// TIA Portal project "SIKO_template_S7_300_UNI_PNvABC_V1.01" (V14)

(* hardware
DEVICE "S7300/ET200M-Station_1"  S7-300 station
   slot 0: "Profilschiene_0"  Rail  6ES7 390-1***0-0AA0
   slot 2: "PLC_1"  CPU 314C-2 PN/DP  6ES7 314-6EH04-0AB0  V3.3
      slot 2: "PROFINET-Schnittstelle_1"  PN-IO
         slot 1: "Port_1"  Port
         slot 2: "Port_2"  Port
      slot 5: "DI 24/DO 16_1"  DI24/DO16
      slot 6: "AI 5/AO 2_1"  AI5/AO2
      slot 7: "Zählen_1"  Counter
      slot 8: "Positionieren_1"  Positioning
DEVICE "GSD-Geraet_1"  GSD.Device.PN
   slot 0: "Baugruppenträger"  Rack  V1.0
   slot 0: "ABC-PRT"  RT Standard  AB7013-C  V3.03
      slot 0: "RT Standard"  RT Standard
      slot 1: "Interface"  Interface
         slot 1: "RJ45 100 MBit/s"  RJ45 100 MBit/s
   slot 1: "Ein-/Ausgänge 004 bytes_1"  Input/Output 004 bytes
      slot 0: "Ein-/Ausgänge 004 bytes"  Input/Output 004 bytes
   slot 2: "Ein-/Ausgänge 016 bytes_1_AG03_1"  Input/Output 016 bytes
      slot 0: "Ein-/Ausgänge 016 bytes"  Input/Output 016 bytes
   slot 3: "Ein-/Ausgänge 016 bytes_1_AG05"  Input/Output 016 bytes
      slot 0: "Ein-/Ausgänge 016 bytes"  Input/Output 016 bytes
   slot 4: "Ein-/Ausgänge 016 bytes_1_AG06"  Input/Output 016 bytes
      slot 0: "Ein-/Ausgänge 016 bytes"  Input/Output 016 bytes
   slot 5: "Ein-/Ausgänge 016 bytes_1_AP04"  Input/Output 016 bytes
      slot 0: "Ein-/Ausgänge 016 bytes"  Input/Output 016 bytes
   slot 6: "Ein-/Ausgänge 016 bytes_1_AP04S"  Input/Output 016 bytes
      slot 0: "Ein-/Ausgänge 016 bytes"  Input/Output 016 bytes
   slot 7: "Ein-/Ausgänge 016 bytes_1_AP10"  Input/Output 016 bytes
      slot 0: "Ein-/Ausgänge 016 bytes"  Input/Output 016 bytes
   slot 8: "Ein-/Ausgänge 016 bytes_1_AP10S"  Input/Output 016 bytes
      slot 0: "Ein-/Ausgänge 016 bytes"  Input/Output 016 bytes
   slot 9: "Ein-/Ausgänge 016 bytes_1_AP10T"  Input/Output 016 bytes
      slot 0: "Ein-/Ausgänge 016 bytes"  Input/Output 016 bytes
*)

// ===== PLC "PLC_1"  CPU 314C-2 PN/DP =====
// protected blocks, not shown: "SIKO_AG03_1_CSW_POS", "SIKO_AG05_CSW_POS", "SIKO_AP04S_CSW_POS", "SIKO_AP04_CSW_POS", "SIKO_AP10S_CSW_POS", "SIKO_AP10T_CSW_POS", "SIKO_AP10_CSW_POS", "SIKO_SN5_COM_EPN", "SIKO_SN5_PARA"

TYPE "DC_Com"
VERSION : 0.1
   STRUCT
      bc00 : Bool;
      bc01 : Bool;
      bc02 : Bool;
      bc03 : Bool;
      bc04 : Bool;
      bc05 : Bool;
      bc06 : Bool;
      bc07 : Bool;
      bc08 : Bool;
      bc09 : Bool;
      bc10 : Bool;
      bc11 : Bool;
      bc12 : Bool;
      bc13 : Bool;
      bc14 : Bool;
      bc15 : Bool;
      bcCal : Bool;
      bs00 : Bool;
      bs01 : Bool;
      bs02 : Bool;
      bs03 : Bool;
      bs04 : Bool;
      bs06 : Bool;
      bs07 : Bool;
      bs08 : Bool;
      bs09 : Bool;
      bs10 : Bool;
      bs11 : Bool;
      bs12 : Bool;
      bs13 : Bool;
      bs14 : Bool;
      bs15 : Bool;
      bsCalExec : Bool;
      nPara1Adr : Byte := BYTE#16#FE;
      nPara2Adr : Byte := BYTE#16#FE;
      nPara3Adr : Byte := BYTE#16#FE;
      nPara3Cmd : Byte;
      nPara3Val : DInt;
      bPara3Write : Bool;
      nPara1AdrRec : Byte;
      nPara1ValRec : DInt;
      nPara2AdrRec : Byte;
      nPara2ValRec : DInt;
      nPara3AdrRec : Byte;
      nPara3ValRec : DInt;
      bPara1FD : Bool;
      bPara2FD : Bool;
      bPara3FD : Bool;
      bsFaultDataRec : Bool;
      nErrCode1 : Byte;
      nErrCode2 : Byte;
      bs05 : Bool;
   END_STRUCT;
END_TYPE

// folder: SystemBlocksFolder/ReportSystemErrorFolder

DATA_BLOCK "RSE_DIAGNOSTIC_STATUS_DB"   // DB127
TITLE = Systemfehler melden Diagnose Baustein
{ S7_Optimized_Access := 'FALSE' }
AUTHOR : SIMATIC
FAMILY : RSEDIAG
NAME : RSE7
VERSION : 1.0
// Dieser DB ist Bestandteil von Systemfehler melden und wird durch den SFM FB aktualisiert.
//  Er ist eine Schnittstelle für die Unterstützung der Systemdiagnose über den CPU Webserver.
   VAR
      Directory : Struct
         D_Version : Word := WORD#16#0100;   // Version, die SFM unterstützt
         D_pGlobalState : Word := WORD#16#0010;   // Byte-Offset bis zum Anfang des Teils "GlobalState"
         D_pQuery : Word := WORD#16#0014;   // Byte-Offset bis zum Anfang des Teils "Query"
         D_pComponent : Word := WORD#16#0020;   // Byte-Offset bis zum Anfang des Teils "Component"
         D_pError : Word := WORD#16#0024;   // Byte-Offset bis zum Anfang des Teils "Error"
         D_pState : Word := WORD#16#0028;   // Byte-Offset bis zum Anfang des Teils "State"
         D_pAlarm : Word := WORD#16#005A;   // Byte-Offset bis zum Anfang des Teils "Alarm"
         D_pSubComponent : Word := WORD#16#0082;   // Byte-Offset bis zum Anfang des Teils "Subcomponent"
      END_STRUCT;
      GlobalState : Struct
         G_EventCount : Word := WORD#16#0000;   // ID des letzten Ereignisses (Zähler)
         G_StartReporting : Bool := FALSE;   // Anlaufauswertung läuft
      END_STRUCT;
      Query : Struct
         Q_ClientID_User : DWord := DWORD#16#0000_0000;   // ID des Clients
         Q_ClientID_Intern : DWord := DWORD#16#0000_0000;   // ID des Clients (intern)
         Q_WithSubComponent : Bool := FALSE;   // Mit/Ohne Status der untergeordneten Komponenten (langsamer)
         Q_SubComponentAlarm : Bool := FALSE;   // AS-iMaster gibt AS-iSlave Alarme zurück
         Q_Reserved2 : Bool := FALSE;   // Reserviert
         Q_Reserved3 : Bool := FALSE;   // Reserviert
         Q_Reserved4 : Bool := FALSE;   // Reserviert
         Q_Reserved5 : Bool := FALSE;   // Reserviert
         Q_Reserved6 : Bool := FALSE;   // Reserviert
         Q_Reserved7 : Bool := FALSE;   // Reserviert
         Q_Start : Bool := FALSE;   // Abfrage starten
         Q_Error : Byte := BYTE#16#00;   // Interner Fehler bei der Abfrage
         Q_Reserved8 : Byte := BYTE#16#00;   // Reserviert
      END_STRUCT;
      Component : Struct
         C_AddressMode : Byte := BYTE#16#00;   // Adressierungsmodus der Baugruppe
         C_Reserved1 : Byte := BYTE#16#00;   // Reserviert
         C_ComponentID : Word := WORD#16#0000;   // Hardware ID der Komponente (intern)
      END_STRUCT;
      Error : Struct
         E_ErrorNo : Word := WORD#16#0000;   // Index des angeforderten/tatsächlichen Fehlers
         E_LastError : Bool := FALSE;   // TRUE, falls E_ErrorNo den Index des letzten Fehlers enthält, ansonsten FALSE
      END_STRUCT;
      State : Struct
         S_Hierarchy : Byte := BYTE#16#00;   // Reserviert
         S_Periphery : Byte := BYTE#16#00;   // Reserviert
         S_SupFault : Bool := FALSE;   // Die Komponente ist nicht erreichbar
         S_NotAvailable : Bool := FALSE;   // Die Komponente ist nicht vorhanden
         S_Faulty : Bool := FALSE;   // Die Komponente ist gestört; der Teil "Alarm" ist nicht leer
         S_MoreErrors : Bool := FALSE;   // Es liegen mehr Fehler an, als SFM speichern kann.
         S_Maintenance1 : Bool := FALSE;   // Ein Wartungsbedarf liegt an
         S_Maintenance2 : Bool := FALSE;   // Eine Wartungsanforderung liegt an
         S_Deactivated : Bool := FALSE;   // Die Komponente wurde deaktiviert
         S_Reserved2 : Bool := FALSE;   // Reserviert
         S_SubFault : Bool := FALSE;   // Eine untergeordnete Komponente ist gestört
         S_SubMaintenance1 : Bool := FALSE;   // Ein Wartungsbedarf liegt an einer untergeordneten Komponente an
         S_SubMaintenance2 : Bool := FALSE;   // Eine Wartungsanforderung liegt an einer untergeordneten Komponente an
         S_SubDeactivated : Bool := FALSE;   // Mindestens eine untergeordnete Komponente ist deaktiviert
         S_Reserved4 : Bool := FALSE;   // Reserviert
         S_Reserved5 : Bool := FALSE;   // Reserviert
         S_Reserved6 : Bool := FALSE;   // Reserviert
         S_Reserved7 : Bool := FALSE;   // Reserviert
         S_TIAMS : DWord := DWORD#16#0000_0000;   // Maintenance State der Komponente
         S_TIAMSChannelExist : DWord := DWORD#16#0000_0000;   // Maintenance State: Projektierte Kanäle
         S_TIAMSChannelOK : DWord := DWORD#16#0000_0000;   // Maintenance State: Gestörte Kanäle
         S_ChannelCount : Word := WORD#16#0000;   // Anzahl Kanäle; nur gültig wenn Q_WithSubComponent gesetzt ist
         S_ChannelVector : Array[0..255] of Bool;   // Liste der betroffenen Kanäle; nur gültig wenn Q_WithSubComponent gesetzt ist
      END_STRUCT;
      Alarm : Struct
         A_ComponentID : Word := WORD#16#0000;   // Hardware-ID der Komponente (intern)
         A_TextID1 : Word := WORD#16#0000;   // ID des ersten Fehlertexts
         A_TextLexikonID1 : Word := WORD#16#0000;   // ID des ersten Fehlertextlexikons
         A_HelpTextLexikonID1 : Word := WORD#16#0000;   // ID des ersten Hilfetextlexikons
         A_MapTextID : Word := WORD#16#0000;   // ID des ersten Fehlertexts in der Exportdatei (HMI)
         A_MapHelpTextID : Word := WORD#16#0000;   // ID des ersten Hilfetexts in der Exportdatei (HMI)
         A_TextID2 : Word := WORD#16#0000;   // ID des zweiten Fehlertexts
         A_TextLexikonID2 : Word := WORD#16#0000;   // ID des zweiten Fehlertextlexikons
         A_HelpTextLexikonID2 : Word := WORD#16#0000;   // ID des zweiten Hilfetextlexikons
         A_MapTextID2 : Word := WORD#16#0000;   // ID des zweiten Fehlertexts in der Exportdatei (HMI)
         A_MapHelpTextID2 : Word := WORD#16#0000;   // ID des zweiten Hilfetexts in der Exportdatei (HMI)
         A_AlarmID : DWord := DWORD#16#0000_0000;   // Meldenummer
         A_ValueCount : Word := WORD#16#000C;   // Anzahl der belegten weiteren Bytes
         A_AssociatedValue : Array[1..6] of Word;   // Begleitwerte der Meldung
      END_STRUCT;
      SubComponent : Struct
         U_SubComponentCount : Word := WORD#16#0000;   // Anzahl der untergeordneten Komponenten
         U_SubComponentFault : Array[1..12] of Byte;   // Liste des Status der untergeordneten Komponenten, 1 Byte pro Komponente
      END_STRUCT;
   END_VAR
BEGIN
END_DATA_BLOCK

// folder: (top level)

ORGANIZATION_BLOCK "OB1"   // OB1, LAD
TITLE = "Main Program Sweep (Cycle)"
{ S7_Optimized_Access := 'FALSE' }
VERSION : 0.1
   VAR_TEMP
      OB1_EV_CLASS : Byte;   // Bits 0-3 = 1 (Coming event), Bits 4-7 = 1 (Event class 1)
      OB1_SCAN_1 : Byte;   // 1 (Cold restart scan 1 of OB 1), 3 (Scan 2-n of OB 1)
      OB1_PRIORITY : Byte;   // Priority of OB Execution
      OB1_OB_NUMBR : Byte;   // 1 (Organization block 1, OB1)
      OB1_RESERVED_1 : Byte;   // Reserved for system
      OB1_RESERVED_2 : Byte;   // Reserved for system
      OB1_PREV_CYCLE : Int;   // Cycle time of previous OB1 scan (milliseconds)
      OB1_MIN_CYCLE : Int;   // Minimum cycle time of OB1 (milliseconds)
      OB1_MAX_CYCLE : Int;   // Maximum cycle time of OB1 (milliseconds)
      OB1_DATE_TIME : Date_And_Time;   // Date and time OB1 started
      DC_Com_AG05 : "DC_Com";
   END_VAR
BEGIN

REGION Network 1
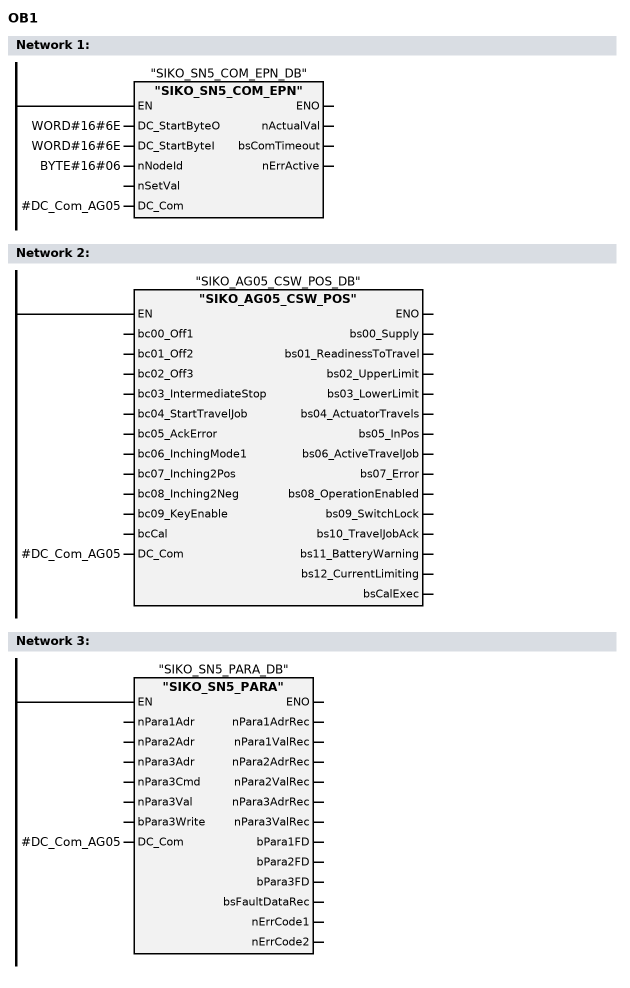
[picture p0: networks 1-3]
   RUNG wire#powerrail
      "SIKO_SN5_COM_EPN_DB"(DC_StartByteO := WORD#16#6E, DC_StartByteI := WORD#16#6E, nNodeId := BYTE#16#06, nSetVal :=, DC_Com := #DC_Com_AG05, nActualVal =>, bsComTimeout =>, nErrActive =>)
   END_RUNG
   // the same network as SCL:
   "SIKO_SN5_COM_EPN_DB"(DC_StartByteO := WORD#16#6E,   // "SIKO_SN5_COM_EPN"
                         DC_StartByteI := WORD#16#6E,
                         nNodeId := BYTE#16#06,
                         DC_Com := #DC_Com_AG05);
END_REGION

REGION Network 2
   RUNG wire#powerrail
      "SIKO_AG05_CSW_POS_DB"(bc00_Off1 :=, bc01_Off2 :=, bc02_Off3 :=, bc03_IntermediateStop :=, bc04_StartTravelJob :=, bc05_AckError :=, bc06_InchingMode1 :=, bc07_Inching2Pos :=, bc08_Inching2Neg :=, bc09_KeyEnable :=, bcCal :=, bs00_Supply =>, bs01_ReadinessToTravel =>, bs02_UpperLimit =>, bs03_LowerLimit =>, bs04_ActuatorTravels =>, bs05_InPos =>, bs06_ActiveTravelJob =>, bs07_Error =>, bs08_OperationEnabled =>, bs09_SwitchLock =>, bs10_TravelJobAck =>, bs11_BatteryWarning =>, bs12_CurrentLimiting =>, bsCalExec =>, DC_Com := #DC_Com_AG05)
   END_RUNG
   // the same network as SCL:
   "SIKO_AG05_CSW_POS_DB"(DC_Com := #DC_Com_AG05);   // "SIKO_AG05_CSW_POS"
END_REGION

REGION Network 3
   RUNG wire#powerrail
      "SIKO_SN5_PARA_DB"(nPara1Adr :=, nPara2Adr :=, nPara3Adr :=, nPara3Cmd :=, nPara3Val :=, bPara3Write :=, DC_Com := #DC_Com_AG05, nPara1AdrRec =>, nPara1ValRec =>, nPara2AdrRec =>, nPara2ValRec =>, nPara3AdrRec =>, nPara3ValRec =>, bPara1FD =>, bPara2FD =>, bPara3FD =>, bsFaultDataRec =>, nErrCode1 =>, nErrCode2 =>)
   END_RUNG
   // the same network as SCL:
   "SIKO_SN5_PARA_DB"(DC_Com := #DC_Com_AG05);   // "SIKO_SN5_PARA"
END_REGION

REGION Network 4 (STL): Call system diagnostics block / Systemdiagnosebaustein aufrufen
         CALL  "RSE_FB", "RSE_DB";
END_REGION
END_ORGANIZATION_BLOCK

ORGANIZATION_BLOCK "OB82"   // OB82, STL
TITLE = "I/O Point Fault"
{ S7_Optimized_Access := 'FALSE' }
VERSION : 0.1
   VAR_TEMP
      OB82_EV_CLASS : Byte;   // 16#39, Event class 3, Entering event state, Internal fault event
      OB82_FLT_ID : Byte;   // 16#XX, Fault identifcation code
      OB82_PRIORITY : Byte;   // Priority of OB Execution
      OB82_OB_NUMBR : Byte;   // 82 (Organization block 82, OB82)
      OB82_RESERVED_1 : Byte;   // Reserved for system
      OB82_IO_FLAG : Byte;   // Input (01010100), Output (01010101)
      OB82_MDL_ADDR : Word;   // Base address of module with fault
      OB82_MDL_DEFECT : Bool;   // Module defective
      OB82_INT_FAULT : Bool;   // Internal fault
      OB82_EXT_FAULT : Bool;   // External fault
      OB82_PNT_INFO : Bool;   // Point information
      OB82_EXT_VOLTAGE : Bool;   // External voltage low
      OB82_FLD_CONNCTR : Bool;   // Field wiring connector missing
      OB82_NO_CONFIG : Bool;   // Module has no configuration data
      OB82_CONFIG_ERR : Bool;   // Module has configuration error
      OB82_MDL_TYPE : Byte;   // Type of module
      OB82_SUB_MDL_ERR : Bool;   // Sub-Module is missing or has error
      OB82_COMM_FAULT : Bool;   // Communication fault
      OB82_MDL_STOP : Bool;   // Module is stopped
      OB82_WTCH_DOG_FLT : Bool;   // Watch dog timer stopped module
      OB82_INT_PS_FLT : Bool;   // Internal power supply fault
      OB82_PRIM_BATT_FLT : Bool;   // Primary battery is in fault
      OB82_BCKUP_BATT_FLT : Bool;   // Backup battery is in fault
      OB82_RESERVED_2 : Bool;   // Reserved for system
      OB82_RACK_FLT : Bool;   // Rack fault, only for bus interface module
      OB82_PROC_FLT : Bool;   // Processor fault
      OB82_EPROM_FLT : Bool;   // EPROM fault
      OB82_RAM_FLT : Bool;   // RAM fault
      OB82_ADU_FLT : Bool;   // ADU fault
      OB82_FUSE_FLT : Bool;   // Fuse fault
      OB82_HW_INTR_FLT : Bool;   // Hardware interupt input in fault
      OB82_RESERVED_3 : Bool;   // Reserved for system
      OB82_DATE_TIME : Date_And_Time;   // Date and time OB82 started
   END_VAR
BEGIN

REGION Network 2: Call system diagnostics block / Systemdiagnosebaustein aufrufen
         CALL  "RSE_FB", "RSE_DB";
END_REGION
END_ORGANIZATION_BLOCK

ORGANIZATION_BLOCK "I/O_FLT2"   // OB83, STL
TITLE = "I/O Point Fault"
{ S7_Optimized_Access := 'FALSE' }
VERSION : 0.1
   VAR_TEMP
      OB83_EV_CLASS : Byte;   // 16#38/39, Event class 3, module inserted/removed (8/9)
      OB83_FLT_ID : Byte;   // 16#XX, Fault identifcation code
      OB83_PRIORITY : Byte;   // Priority of OB Execution
      OB83_OB_NUMBR : Byte;   // 83 (Organization block 83, OB83)
      OB83_RESERVED_1 : Byte;   // Reserved for system
      OB83_MDL_ID : Byte;   // Input module (01010100), Output module (01010101)
      OB83_MDL_ADDR : Word;   // Base address of module with point fault
      OB83_RACK_NUM : Int;   // Number of rack that has module with point fault
      OB83_MDL_TYPE : Word;   // Module type with point fault
      OB83_DATE_TIME : Date_And_Time;   // Date and time OB83 started
   END_VAR
BEGIN

REGION Network 1: Call system diagnostics block / Systemdiagnosebaustein aufrufen
         CALL  "RSE_FB", "RSE_DB";
END_REGION
END_ORGANIZATION_BLOCK

ORGANIZATION_BLOCK "OBNL_FLT"   // OB85, STL
TITLE = "Organization Block (OB) Not Loaded Fault"
{ S7_Optimized_Access := 'FALSE' }
VERSION : 0.1
   VAR_TEMP
      OB85_EV_CLASS : Byte;   // 16#35 Event class 3
      OB85_FLT_ID : Byte;   // 16#XX, Fault identification code
      OB85_PRIORITY : Byte;   // Priority of OB Execution
      OB85_OB_NUMBR : Byte;   // 85 (Organization block 85, OB85)
      OB85_RESERVED_1 : Byte;   // Reserved for system
      OB85_RESERVED_2 : Byte;   // Reserved for system
      OB85_RESERVED_3 : Int;   // Reserved for system
      OB85_ERR_EV_CLASS : Byte;   // Class of event causing error
      OB85_ERR_EV_NUM : Byte;   // Number of event causing error
      OB85_OB_PRIOR : Byte;   // Priority of OB causing error
      OB85_OB_NUM : Byte;   // Number of OB causing error
      OB85_DATE_TIME : Date_And_Time;   // Date and time OB85 started
   END_VAR
BEGIN

REGION Network 1
         L     b#16#A1;  //
         L     #OB85_FLT_ID;
         ==I;
         JC    K_OB;
         L     b#16#A2;  //
         ==I;
         JC    K_OB;
         L     b#16#A3;  //
         L     #OB85_FLT_ID;
         ==I;
         JC    K_B;
         JU    F_PA;
END_REGION

REGION Network 2
   K_OB: JU    STOP;
         JU    ENDE;
END_REGION

REGION Network 3
   K_B:  JU    STOP;
         JU    ENDE;
END_REGION

REGION Network 4
   F_PA: NOP   0;
         JU    ENDE;
END_REGION

REGION Network 5
   STOP: CALL  STP;
END_REGION

REGION Network 6

   //

   ENDE: NOP   0;
END_REGION
END_ORGANIZATION_BLOCK

ORGANIZATION_BLOCK "OB86"   // OB86, STL
TITLE = "Loss Of Rack Fault"
{ S7_Optimized_Access := 'FALSE' }
VERSION : 0.1
   VAR_TEMP
      OB86_EV_CLASS : Byte;   // 16#38/39 Event class 3
      OB86_FLT_ID : Byte;   // 16#C1/C4/C5, Fault identifcation code
      OB86_PRIORITY : Byte;   // Priority of OB Execution
      OB86_OB_NUMBR : Byte;   // 86 (Organization block 86, OB86)
      OB86_RESERVED_1 : Byte;   // Reserved for system
      OB86_RESERVED_2 : Byte;   // Reserved for system
      OB86_MDL_ADDR : Word;   // Base address of IM module in rack with fault
      OB86_RACKS_FLTD : Array[0..31] of Bool;
      OB86_DATE_TIME : Date_And_Time;   // Date and time OB86 started
   END_VAR
BEGIN

REGION Network 2: Call system diagnostics block / Systemdiagnosebaustein aufrufen
         CALL  "RSE_FB", "RSE_DB";
END_REGION
END_ORGANIZATION_BLOCK

ORGANIZATION_BLOCK "OB122"   // OB122, STL
TITLE = "Module Access Error"
{ S7_Optimized_Access := 'FALSE' }
VERSION : 0.1
   VAR_TEMP
      OB122_EV_CLASS : Byte;   // 16#29, Event class 2, Entering event state, Internal fault event
      OB122_SW_FLT : Byte;   // 16#XX Software error code
      OB122_PRIORITY : Byte;   // X = Priority of OB where fault occured (Priority of 1 is lowest)
      OB122_OB_NUMBR : Byte;   // 122 (Organization block 122, OB122)
      OB122_BLK_TYPE : Byte;   // 16#88/8A/8C/8E Type of block fault occured in
      OB122_MEM_AREA : Byte;   // Memory area where access error occured
      OB122_MEM_ADDR : Word;   // Memory address where access error occured
      OB122_BLK_NUM : Word;   // Block number in which error occured
      OB122_PRG_ADDR : Word;   // Program address where error occured
      OB122_DATE_TIME : Date_And_Time;   // Date and time OB1 started
   END_VAR
BEGIN
END_ORGANIZATION_BLOCK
